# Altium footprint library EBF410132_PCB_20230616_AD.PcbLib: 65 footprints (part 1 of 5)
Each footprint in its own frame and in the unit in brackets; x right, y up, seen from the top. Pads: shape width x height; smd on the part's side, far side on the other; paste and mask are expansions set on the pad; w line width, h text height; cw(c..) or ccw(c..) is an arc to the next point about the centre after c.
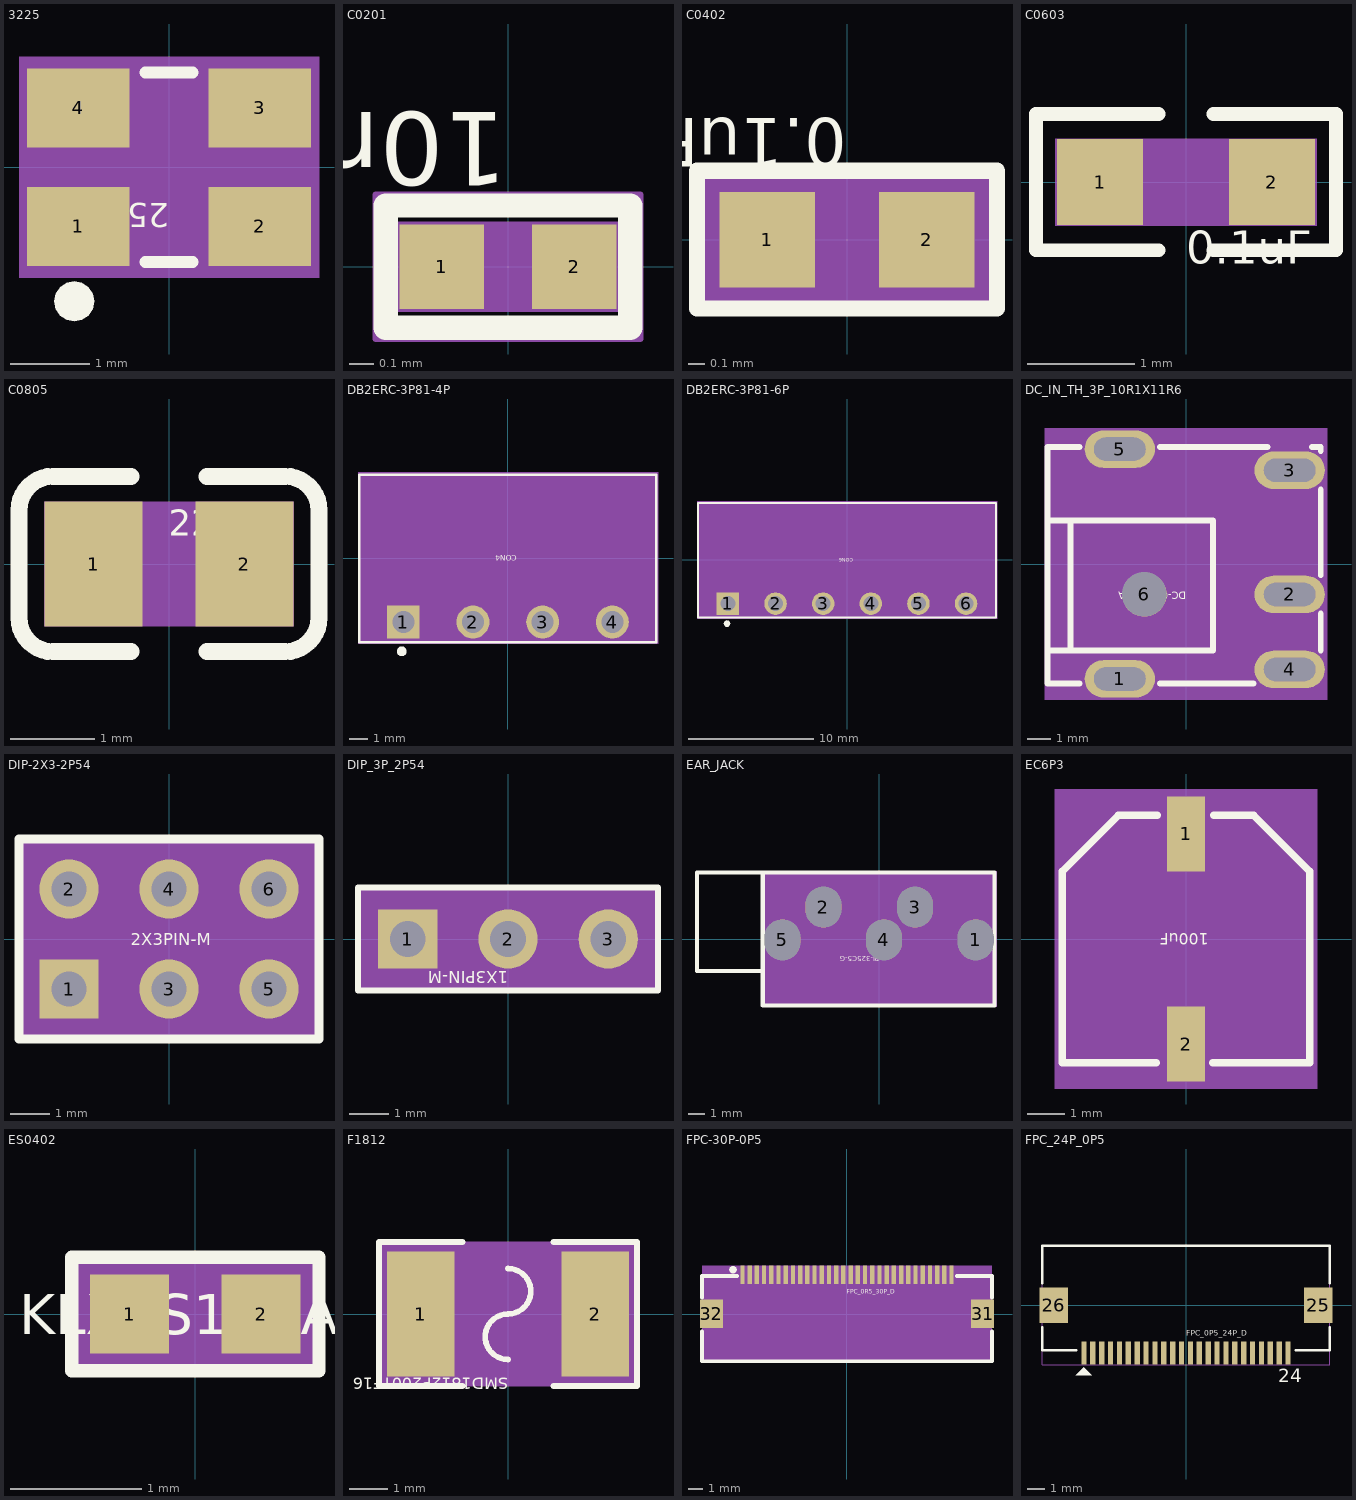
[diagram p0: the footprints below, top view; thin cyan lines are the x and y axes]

## 3225 [mm] "3225"
pads (4):
  rect 1.3x1 smd: 1(-1.15,-0.75) 2(1.15,-0.75) 3(1.15,0.75) 4(-1.15,0.75)
Top Overlay:
  dashed: -1.2,-1.445 -1.298,-1.465 -1.38,-1.52 -1.435,-1.602 -1.455,-1.7 -1.435,-1.798 -1.417,-1.825 -1.38,-1.88 -1.298,-1.935 -1.2,-1.955 -1.102,-1.935 -1.02,-1.88 -0.983,-1.825 -0.965,-1.798 -0.945,-1.7 -0.965,-1.602 -1.02,-1.52 -1.102,-1.465
  lines w0.15: -0.3,-1.2 0.3,-1.2 ; -0.3,1.2 0.3,1.2
  text "25MHz" at 0,-0.457 h0.3
Top 3D Body:
  region: -1.9,1.4 -1.9,-1.4 1.9,-1.4 1.9,1.4
Mechanical 15:
  text "2" at 1.15,-1.106 h0.89
  text "4" at -1.15,0.394 h0.89
  text "3" at 1.15,0.394 h0.89
  text "1" at -1.15,-1.106 h0.89
Top Assembly:
  lines w0.15: -1.6,-1.25 -1.6,1.25 1.6,1.25 1.6,-1.25 -1.6,-1.25
3D body: height 3.81, standoff 0, extent -1.9,-1.4 1.9,1.4

## C0201 [mm] "C0201"
pads (2):
  rect 0.35x0.35 smd: 1(-0.275,0) 2(0.275,0)
Top Overlay:
  lines w0.102: -0.508,-0.254 0.508,-0.254 0.508,0.254 -0.508,0.254 -0.508,-0.254
  text "10nF" at 0,0.64 h0.3
Top 3D Body:
  region: -0.475,-0.175 -0.475,0.175 0.475,0.175 0.475,-0.175
Mechanical 15:
  text "2" at 0.275,0.305 h0.76
  text "1" at -0.275,0.305 h0.76
Top Assembly:
  lines w0.025: -0.55,-0.3 -0.55,0.3 0.55,0.3 0.55,-0.3 -0.55,-0.3 ; -0.475,-0.175 -0.475,0.175 0.475,0.175 0.475,-0.175 -0.475,-0.175
  text ".Designator" at 0.508,0.254 h0.76
  text "10nF" at 0.762,-0.254 h0.76
3D body: height 3.81, standoff 0, extent -0.475,-0.175 0.475,0.175

## C0402 [mm] "C0402"
pads (2):
  rect 0.599x0.599 smd: 1(-0.5,0) 2(0.5,0)
Top Overlay:
  lines w0.102: -0.94,-0.432 0.94,-0.432 0.94,0.432 -0.94,0.432 -0.94,-0.432
  text "0.1uF" at 0,0.762 h0.3
Top 3D Body:
  region: 0.94,0.432 0.94,-0.432 -0.94,-0.432 -0.94,0.432
Mechanical 15:
  text "1" at -0.5,0.254 h0.64
  text "2" at 0.5,0.254 h0.64
Top Assembly:
  dashed: -0.94,-0.432 -0.94,0.432 0.94,0.432 0.94,-0.432
3D body: height 3.81, standoff 0, extent -0.94,-0.432 0.94,0.432

## C0603 [mil] "C0603"
pads (2):
  rect 31.5x31.5 smd: 1(-31.5,0) 2(31.5,0)
Top Overlay:
  lines w5: -10,-25 -55,-25 -55,25 -10,25 ; 10,-25 55,-25 55,25 10,25
  text "0.1uF" at 0.01,-30 h12
Top 3D Body:
  region: -48,16 48,16 48,-16 -48,-16
Mechanical 15:
  text "1" at -31.5,-18 h45
  text "2" at 31.5,-18 h45
Top Assembly:
  text "C0603" at -117,37 h35
3D body: height 150, standoff 0, extent -48,-16 48,16

## C0805 [mm] "C0805"
pads (2):
  rect 1.16x1.47 smd: 1(-0.89,0) 2(0.89,0)
Top Overlay:
  lines w0.2: -0.45,-1.035 -1.37,-1.035 cw(c-1.37,-0.635) -1.77,-0.635 -1.77,0.635 cw(c-1.37,0.635) -1.37,1.035 -0.45,1.035 ; 0.45,-1.035 1.37,-1.035 ccw(c1.37,-0.635) 1.77,-0.635 1.77,0.635 ccw(c1.37,0.635) 1.37,1.035 0.45,1.035
  text "22uF" at 0,0.335 h0.3
Top 3D Body:
  region: -1.47,-0.735 1.47,-0.735 1.47,0.735 -1.47,0.735
Mechanical 15:
  text "2" at 0.89,0.315 h0.79
  text "1" at -0.89,0.315 h0.79
3D body: height 3.81, standoff 0, extent -1.47,-0.735 1.47,0.735

## DB2ERC-3P81-4P [mm] "DB2ERC-3P81-4P"
pads (4):
  rect 1.8x1.8 hole 1.2: 1(-5.725,-3.5)
  round 1.8 hole 1.2: 2(-1.915,-3.5) 3(1.895,-3.5) 4(5.705,-3.5)
Top Overlay:
  dashed: -6.065,-5.1 -6.045,-5.198 -5.99,-5.28 -5.908,-5.336 -5.81,-5.355 -5.712,-5.336 -5.685,-5.317 -5.63,-5.28 -5.574,-5.198 -5.555,-5.1 -5.574,-5.002 -5.63,-4.92 -5.685,-4.883 -5.712,-4.865 -5.81,-4.845 -5.908,-4.865 -5.99,-4.92 -6.045,-5.002
  lines w0.15: -8.13,-4.6 8.11,-4.6 8.11,4.55 -8.13,4.55 -8.13,-4.6
  text "CON4" at 0.488,0.152 h0.3
Top 3D Body:
  region: -8.2,4.7 -8.2,-4.7 8.2,-4.7 8.2,4.7
Mechanical 15:
  text "4" at 5.959,-3.5 h0.64
  text "3" at 2.149,-3.5 h0.64
  text "2" at -1.661,-3.5 h0.64
  text "1" at -5.471,-3.5 h0.64
3D body: height 3.81, standoff 0, extent -8.2,-4.7 8.2,4.7

## DB2ERC-3P81-6P [mm] "DB2ERC-3P81-6P"
pads (6):
  rect 1.8x1.8 hole 1.2: 1(-9.525,-3.5)
  round 1.8 hole 1.2: 2(-5.715,-3.5) 3(-1.905,-3.5) 4(1.905,-3.5) 5(5.715,-3.5) 6(9.525,-3.5)
Top Overlay:
  dashed: -9.855,-5.1 -9.836,-5.198 -9.78,-5.28 -9.698,-5.336 -9.6,-5.355 -9.502,-5.336 -9.475,-5.317 -9.42,-5.28 -9.364,-5.198 -9.345,-5.1 -9.364,-5.002 -9.42,-4.92 -9.475,-4.883 -9.502,-4.865 -9.6,-4.845 -9.698,-4.865 -9.78,-4.92 -9.836,-5.002
  lines w0.15: -11.93,-4.6 11.93,-4.6 11.93,4.55 -11.93,4.55 -11.93,-4.6
  text "CON6" at 0.488,0.152 h0.3
Top 3D Body:
  region: -12,4.7 -12,-4.7 12,-4.7 12,4.7
Mechanical 15:
  text "5" at 5.969,-3.5 h0.64
  text "2" at -5.461,-3.5 h0.64
  text "6" at 9.779,-3.5 h0.64
  text "4" at 2.159,-3.5 h0.64
  text "3" at -1.651,-3.5 h0.64
  text "1" at -9.271,-3.5 h0.64
3D body: height 3.81, standoff 0, extent -12,-4.7 12,4.7

## DC_IN_TH_3P_10R1X11R6 [mm] "DC_IN_TH_3P_10R1X11R6"
pads (6):
  oval 3x1.6 hole 2.2 slot 1 at 90 deg: 1(-2.825,-4.9) 2(4.425,-1.3) 3(4.425,4) 4(4.425,-4.5) 5(-2.825,4.9)
  round 1.9 hole 1.9 unplated: 6(-1.775,-1.3)
Top Overlay:
  lines w0.254: -5.9,-3.7 1.15,-3.7 1.15,1.85 -5.65,1.85 -5.9,1.85 ; -4.926,-3.7 -4.926,1.85 ; -4.545,-5.1 -5.9,-5.1 -5.9,5 -4.545,5 ; -1.105,-5.1 2.887,-5.1 ; -1.105,5 3.478,5 ; 5.372,5 5.75,5 5.75,4.82 ; 5.75,-3.681 5.75,-2.119 ; 5.75,-0.481 5.75,3.182
  text "DC-044A-20A" at 0,-1.189 h0.3
Top 3D Body:
  region: -6.027,-5.802 6.027,-5.802 6.027,5.802 -6.027,5.802
Mechanical 15:
  text "2" at 4.425,-1.554 h0.64
  text "3" at 4.425,3.746 h0.64
  text "4" at 4.425,-4.754 h0.64
  text "1" at -2.825,-5.154 h0.64
  text "5" at -2.825,4.646 h0.64
  text "6" at -1.775,-1.554 h0.64
Top Assembly:
  text ".Designator" at 0.8,0 h0.91
Mechanical 23:
  dashed: -5.9,-3.6 1.05,-3.6 1.05,1.75 -5.9,1.75 -5.9,2 1.3,2 1.3,-3.85 -5.9,-3.85
3D body: height 3.81, standoff 0, extent -6.027,-5.802 6.027,5.802

## DIP-2X3-2P54 [mm] "DIP-2X3-2P54"
pads (6):
  rect 1.5x1.5 hole 0.9: 1(-2.54,-1.27)
  round 1.5 hole 0.9: 2(-2.54,1.27) 3(0,-1.27) 4(0,1.27) 5(2.54,-1.27) 6(2.54,1.27)
Top Overlay:
  lines w0.22: -3.54,2.54 -3.81,2.54 ; -3.81,2.54 3.81,2.54 3.81,-2.54 -3.81,-2.54 -3.81,2.54
  text "2X3PIN-M" at -0.975,-0.152 h0.3
Top 3D Body:
  region: -3.81,-2.54 3.81,-2.54 3.81,2.54 -3.81,2.54
Mechanical 15:
  text "6" at 2.286,1.27 h0.64
  text "5" at 2.286,-1.27 h0.64
  text "2" at -2.794,1.27 h0.64
  text "1" at -2.794,-1.27 h0.64
  text "3" at -0.254,-1.27 h0.64
  text "4" at -0.254,1.27 h0.64
Top Assembly:
  text ".Designator" at -3.683,2.464 h0.3
3D body: height 3.81, standoff 0, extent -3.81,-2.54 3.81,2.54

## DIP_3P_2P54 [mm] "DIP_3P_2P54"
pads (3):
  rect 1.5x1.5 hole 0.9: 1(-2.54,0)
  round 1.5 hole 0.9: 2(0,0) 3(2.54,0)
Top Overlay:
  lines w0.15: -3.8,-1.3 -3.8,1.3 3.8,1.3 3.8,-1.3 -3.8,-1.3
  text "1X3PIN-M" at 0,-0.823 h0.3
Top 3D Body:
  region: -3.8,-1.3 3.8,-1.3 3.8,1.3 -3.8,1.3
Mechanical 15:
  text "3" at 2.54,-0.254 h0.64
  text "2" at 0,-0.254 h0.64
  text "1" at -2.54,-0.254 h0.64
Top Assembly:
  lines w0.025: -3.8,-1.3 3.8,-1.3 3.8,1.3 -3.8,1.3 -3.8,-1.3
3D body: height 3.81, standoff 0, extent -3.8,-1.3 3.8,1.3

## EAR_JACK [mil] "EAR_JACK"
pads (5):
  oval 86x98 hole 86 slot 98 at 90 deg: 1(232.28,-1.97) 2(-133.86,76.77) 3(86.61,76.77) 4(11.81,-1.97) 5(-232.29,-1.97)
Top Overlay:
  lines w10: -282.68,-77 -437.68,-77 -437.68,160 -282.68,160 ; -279.68,-160 -279.68,160 277.32,160 277.32,-160 -279.68,-160
  text "PJ-325C5-G" at 0.01,-42 h12
Top 3D Body:
  region: -283.46,-163.38 283.46,-163.38 283.46,163.39 -283.46,163.39
Mechanical 15:
  text "3" at 86.61,66.77 h25
  text "4" at 11.81,-11.97 h25
  text "2" at -133.86,66.77 h25
  text "1" at 232.28,-11.97 h25
  text "5" at -232.29,-11.97 h25
Top Assembly:
  dashed: -283.46,163.39 -283.46,-163.38 283.46,-163.38 283.46,163.39
  text ".Designator" at -440.72,172.03 h11.81
3D body: height 150, standoff 0, extent -283.46,-163.38 283.46,163.39

## EC6P3 [mm] "EC6P3"
pads (2):
  rect 1.001x1.999 smd: 1(0,2.8) 2(0,-2.8)
Top Overlay:
  lines w0.2: -0.787,-3.3 -3.3,-3.3 -3.3,1.8 -1.8,3.3 -0.762,3.3 ; 0.711,-3.3 3.3,-3.3 3.3,1.8 1.8,3.3 0.737,3.3
  text "100uF" at 0.61,0.152 h0.3
Top 3D Body:
  region: -3.5,4 -3.5,-4 3.5,-4 3.5,4
Mechanical 15:
  text "1" at 0.356,2.8 h0.89
  text "2" at 0.356,-2.8 h0.89
3D body: height 3.81, standoff 0, extent -3.5,-4 3.5,4

## ES0402 [mm] "ES0402"
pads (2):
  rect 0.599x0.599 smd: 1(-0.5,0) 2(0.5,0)
Top Overlay:
  lines w0.102: -0.94,-0.432 0.94,-0.432 0.94,0.432 -0.94,0.432 -0.94,-0.432
  text "KLXES15AAA1" at -1.341,-0.152 h0.3
Top 3D Body:
  region: 0.94,0.432 0.94,-0.432 -0.94,-0.432 -0.94,0.432
Mechanical 15:
  text "2" at 0.246,0 h0.64
  text "1" at -0.754,0 h0.64
Top Assembly:
  dashed: -0.94,-0.432 -0.94,0.432 0.94,0.432 0.94,-0.432
3D body: height 3.81, standoff 0, extent -0.94,-0.432 0.94,0.432

## F1812 [mm] "F1812"
pads (2):
  rect 1.78x3.3 smd: 1(-2.305,0) 2(2.305,0)
Top Overlay:
  lines w0.15: -1.2,-1.9 -3.4,-1.9 -3.4,1.9 -1.2,1.9 ; 0,-1.2 cw(c0,-0.6) 0,0 ccw(c0,0.6) 0,1.2 ; 1.2,-1.9 3.4,-1.9 3.4,1.9 1.2,1.9
  text "SMD1812P200TF16" at 0,-1.676 h0.3
Top 3D Body:
  region: -3.4,-1.9 3.4,-1.9 3.4,1.9 -3.4,1.9
Mechanical 15:
  text "2" at 2.305,-0.122 h0.3
  text "1" at -2.305,-0.122 h0.3
3D body: height 3.81, standoff 0, extent -3.4,-1.9 3.4,1.9

## FPC-30P-0P5 [mm] "FPC-30P-0P5"
pads (32):
  rect 0.3x1.3 smd: 1(-7.25,2.733) 2(-6.75,2.733) 3(-6.25,2.733) 4(-5.75,2.733) 5(-5.25,2.733) 6(-4.75,2.733) 7(-4.25,2.733) 8(-3.75,2.733) 9(-3.25,2.733) 10(-2.75,2.733) 11(-2.25,2.733) 12(-1.75,2.733) 13(-1.25,2.733) 14(-0.75,2.733) 15(-0.25,2.733) 16(0.25,2.733) 17(0.75,2.733) 18(1.25,2.733) 19(1.75,2.733) 20(2.25,2.733) 21(2.75,2.733) 22(3.25,2.733) 23(3.75,2.733) 24(4.25,2.733) 25(4.75,2.733) 26(5.25,2.733) 27(5.75,2.733) 28(6.25,2.733) 29(6.75,2.733) 30(7.25,2.733)
  rect 1.6x2 smd: 31(9.4,0.032) 32(-9.4,0.032)
Top Overlay:
  dashed: -7.9,2.828 -7.802,2.847 -7.72,2.902 -7.664,2.985 -7.645,3.082 -7.664,3.18 -7.683,3.208 -7.72,3.263 -7.802,3.318 -7.9,3.337 -7.997,3.318 -8.08,3.263 -8.117,3.208 -8.135,3.18 -8.155,3.082 -8.135,2.985 -8.08,2.902 -7.997,2.847
  lines w0.254: -10.05,-1.199 -10.05,-3.257 ; -10.05,1.164 -10.05,2.652 -7.631,2.652 ; 7.631,2.652 10.05,2.652 10.05,1.164 ; 10.05,-1.199 10.05,-3.268 -10.04,-3.268 -10.05,-3.257 ; -10.05,-3.257 -10.05,-3.257
  text "FPC_0R5_30P_D" at 0,1.433 h0.3
Top 3D Body:
  region: 10.052,-3.35 10.052,3.35 -10.052,3.35 -10.052,-3.35
Mechanical 15:
  text "10" at -2.75,3.749 h0.64
  text "9" at -3.25,3.241 h0.64
  text "29" at 6.75,3.749 h0.64
  text "28" at 6.25,3.749 h0.64
  text "27" at 5.75,3.749 h0.64
  text "26" at 5.25,3.749 h0.64
  text "21" at 2.75,3.749 h0.64
  text "20" at 2.25,3.749 h0.64
  text "19" at 1.75,3.749 h0.64
  text "18" at 1.25,3.749 h0.64
  text "16" at 0.25,3.749 h0.64
  text "15" at -0.25,3.749 h0.64
  text "11" at -2.25,3.749 h0.64
  text "8" at -3.75,3.241 h0.64
  text "5" at -5.25,3.241 h0.64
  text "2" at -6.75,3.241 h0.64
  text "32" at -10.16,0.112 h0.64
  text "31" at 8.89,0.112 h0.64
  text "7" at -4.25,3.241 h0.64
  text "3" at -6.25,3.241 h0.64
  text "17" at 0.75,3.749 h0.64
  text "4" at -5.75,3.241 h0.64
  text "6" at -4.75,3.241 h0.64
  text "23" at 3.75,3.749 h0.64
  text "13" at -1.25,3.749 h0.64
  text "12" at -1.75,3.749 h0.64
  text "22" at 3.25,3.749 h0.64
  text "30" at 7.25,3.749 h0.64
  text "25" at 4.75,3.749 h0.64
  text "24" at 4.25,3.749 h0.64
  text "14" at -0.75,3.749 h0.64
  text "1" at -7.25,3.241 h0.64
3D body: height 3.81, standoff 0, extent -10.052,-3.35 10.052,3.35

## FPC_24P_0P5 [mm] "FPC_24P_0P5"
pads (26):
  rect 0.3x1.3 smd: 1(-5.75,-2.701) 2(-5.25,-2.701) 3(-4.75,-2.701) 4(-4.25,-2.701) 5(-3.75,-2.701) 6(-3.25,-2.701) 7(-2.75,-2.701) 8(-2.25,-2.701) 9(-1.75,-2.701) 10(-1.25,-2.701) 11(-0.75,-2.701) 12(-0.25,-2.701) 13(0.25,-2.701) 14(0.75,-2.701) 15(1.25,-2.701) 16(1.75,-2.701) 17(2.25,-2.701) 18(2.75,-2.701) 19(3.25,-2.701) 20(3.75,-2.701) 21(4.25,-2.701) 22(4.75,-2.701) 23(5.25,-2.701) 24(5.75,-2.701)
  rect 1.6x2 smd: 25(7.45,0.001) 26(-7.45,0.001)
Top Overlay:
  dashed: -6.199,-3.95 -5.301,-3.95 -5.75,-3.501
  lines w0.15: -8.1,-1.25 -8.1,-2.55 -6.2,-2.55 ; -8.1,1.25 -8.1,3.35 8.1,3.35 8.1,1.25 ; 6.2,-2.55 8.1,-2.55 8.1,-1.25
  text "FPC_0P5_24P_D" at 0,-1.737 h0.3
  text "24" at 5.2,-4.35 h0.76
Top 3D Body:
  lines w0.025: -8.1,-3.35 -8.1,3.35 8.1,3.35 8.1,-3.35 -8.1,-3.35
Mechanical 15:
  text "20" at 3.75,-3.209 h0.64
  text "19" at 3.25,-3.209 h0.64
  text "17" at 2.25,-3.209 h0.64
  text "16" at 1.75,-3.209 h0.64
  text "5" at -3.75,-2.955 h0.64
  text "6" at -3.25,-2.955 h0.64
  text "4" at -4.25,-2.955 h0.64
  text "23" at 5.25,-3.209 h0.64
  text "24" at 5.75,-3.209 h0.64
  text "26" at -7.45,-0.507 h0.64
  text "25" at 7.45,-0.507 h0.64
  text "21" at 4.25,-3.209 h0.64
  text "18" at 2.75,-3.209 h0.64
  text "12" at -0.25,-3.209 h0.64
  text "11" at -0.75,-3.209 h0.64
  text "10" at -1.25,-3.209 h0.64
  text "9" at -1.75,-2.955 h0.64
  text "8" at -2.25,-2.955 h0.64
  text "7" at -2.75,-2.955 h0.64
  text "22" at 4.75,-3.209 h0.64
  text "15" at 1.25,-3.209 h0.64
  text "3" at -4.75,-2.955 h0.64
  text "2" at -5.25,-2.955 h0.64
  text "1" at -5.75,-2.955 h0.64
  text "14" at 0.75,-3.209 h0.64
  text "13" at 0.25,-3.209 h0.64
